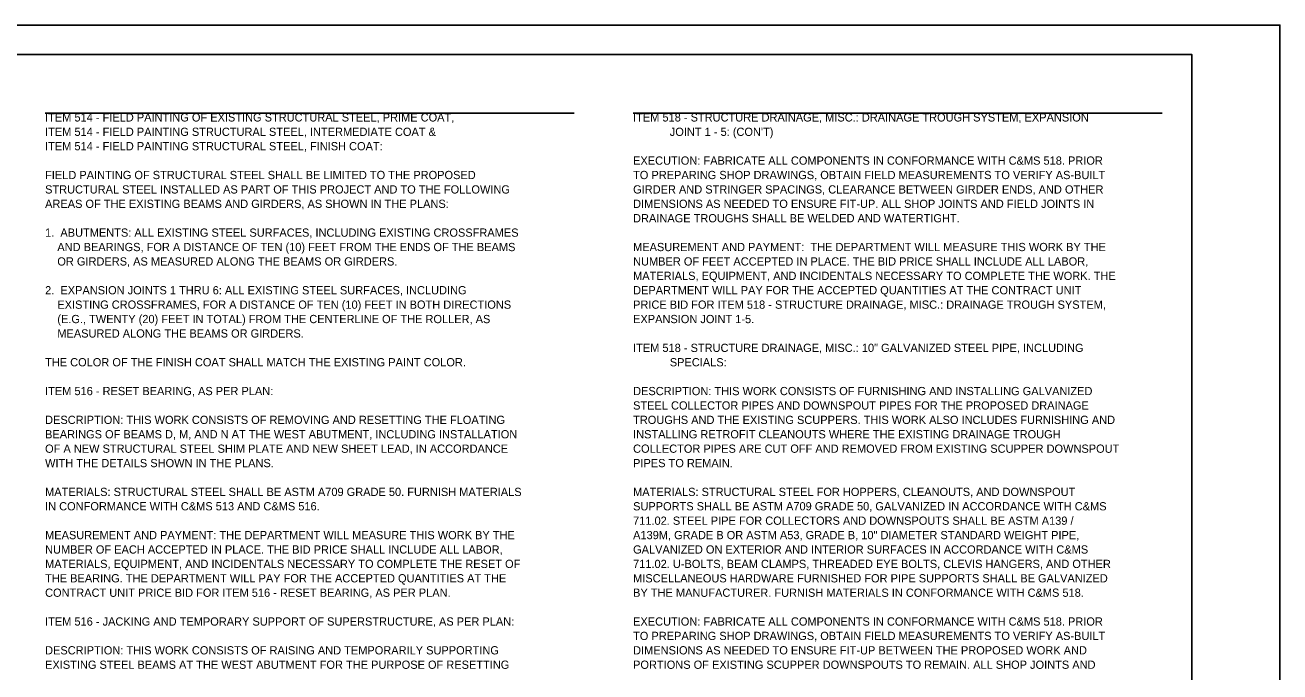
# Model space of a CAD drawing. Extents: x 0 to 72, y -26 to 50.
# Drawn here: x 50.66 to 72, y 37 to 48 of the extents above; entities that cross this region are included whole.
import ezdxf

# ---------------------------------------------------------------- set-up
doc = ezdxf.new("R2010")
doc.units = 0
doc.layers.add('SH_Cut_Line', color=7, linetype='Continuous')
doc.layers.add('SH_Data', color=7, linetype='Continuous')

msp = doc.modelspace()

# ---------------------------------------------------------------- linework, layer by layer
at = {"layer": 'SH_Cut_Line'}
for p, q in [((51, 46.5), (60, 46.5)), ((61, 46.5), (70, 46.5))]:
    msp.add_line(p, q, dxfattribs=at)
for points in [[(38, 48), (72, 48), (72, 26), (38, 26)], [(40, 47.5), (70.5, 47.5), (70.5, 26.5), (40, 26.5)]]:
    msp.add_lwpolyline(points, close=True, dxfattribs=at)

# ---------------------------------------------------------------- texts
at = {"layer": 'SH_Data'}
for s, p in [('ITEM 514 - FIELD PAINTING OF EXISTING STRUCTURAL STEEL, PRIME COAT,', (51, 46.36)), ('ITEM 514 - FIELD PAINTING OF EXISTING STRUCTURAL STEEL, PRIME COAT,', (51, 46.36)), ('ITEM 518 - STRUCTURE DRAINAGE, MISC.: DRAINAGE TROUGH SYSTEM, EXPANSION', (61, 46.36)), ('ITEM 518 - STRUCTURE DRAINAGE, MISC.: DRAINAGE TROUGH SYSTEM, EXPANSION', (61, 46.36)), ('ITEM 514 - FIELD PAINTING STRUCTURAL STEEL, INTERMEDIATE COAT &', (51, 46.115)), ('ITEM 514 - FIELD PAINTING STRUCTURAL STEEL, INTERMEDIATE COAT &', (51, 46.115)), ("            JOINT 1 - 5: (CON'T)", (61, 46.115)), ("            JOINT 1 - 5: (CON'T)", (61, 46.115)), ('ITEM 514 - FIELD PAINTING STRUCTURAL STEEL, FINISH COAT:', (51, 45.87)), ('ITEM 514 - FIELD PAINTING STRUCTURAL STEEL, FINISH COAT:', (51, 45.87)), ('EXECUTION: FABRICATE ALL COMPONENTS IN CONFORMANCE WITH C&MS 518. PRIOR ', (61, 45.625)), ('FIELD PAINTING OF STRUCTURAL STEEL SHALL BE LIMITED TO THE PROPOSED ', (51, 45.38)), ('TO PREPARING SHOP DRAWINGS, OBTAIN FIELD MEASUREMENTS TO VERIFY AS-BUILT ', (61, 45.38)), ('STRUCTURAL STEEL INSTALLED AS PART OF THIS PROJECT AND TO THE FOLLOWING ', (51, 45.135)), ('GIRDER AND STRINGER SPACINGS, CLEARANCE BETWEEN GIRDER ENDS, AND OTHER ', (61, 45.135)), ('AREAS OF THE EXISTING BEAMS AND GIRDERS, AS SHOWN IN THE PLANS:', (51, 44.89)), ('DIMENSIONS AS NEEDED TO ENSURE FIT-UP. ALL SHOP JOINTS AND FIELD JOINTS IN ', (61, 44.89)), ('DRAINAGE TROUGHS SHALL BE WELDED AND WATERTIGHT.', (61, 44.645)), ('1.  ABUTMENTS: ALL EXISTING STEEL SURFACES, INCLUDING EXISTING CROSSFRAMES ', (51, 44.4)), ('    AND BEARINGS, FOR A DISTANCE OF TEN (10) FEET FROM THE ENDS OF THE BEAMS ', (51, 44.155)), ('MEASUREMENT AND PAYMENT:  THE DEPARTMENT WILL MEASURE THIS WORK BY THE ', (61, 44.155)), ('    OR GIRDERS, AS MEASURED ALONG THE BEAMS OR GIRDERS.', (51, 43.91)), ('NUMBER OF FEET ACCEPTED IN PLACE. THE BID PRICE SHALL INCLUDE ALL LABOR, ', (61, 43.91)), ('MATERIALS, EQUIPMENT, AND INCIDENTALS NECESSARY TO COMPLETE THE WORK. THE ', (61, 43.665)), ('2.  EXPANSION JOINTS 1 THRU 6: ALL EXISTING STEEL SURFACES, INCLUDING', (51, 43.42)), ('DEPARTMENT WILL PAY FOR THE ACCEPTED QUANTITIES AT THE CONTRACT UNIT ', (61, 43.42)), ('    EXISTING CROSSFRAMES, FOR A DISTANCE OF TEN (10) FEET IN BOTH DIRECTIONS', (51, 43.175)), ('PRICE BID FOR ITEM 518 - STRUCTURE DRAINAGE, MISC.: DRAINAGE TROUGH SYSTEM, ', (61, 43.175)), ('    (E.G., TWENTY (20) FEET IN TOTAL) FROM THE CENTERLINE OF THE ROLLER, AS', (51, 42.93)), ('EXPANSION JOINT 1-5.', (61, 42.93)), ('    MEASURED ALONG THE BEAMS OR GIRDERS.', (51, 42.685)), ('ITEM 518 - STRUCTURE DRAINAGE, MISC.: 10" GALVANIZED STEEL PIPE, INCLUDING', (61, 42.44)), ('ITEM 518 - STRUCTURE DRAINAGE, MISC.: 10" GALVANIZED STEEL PIPE, INCLUDING', (61, 42.44)), ('THE COLOR OF THE FINISH COAT SHALL MATCH THE EXISTING PAINT COLOR.', (51, 42.195)), ('            SPECIALS:', (61, 42.195)), ('            SPECIALS:', (61, 42.195)), ('ITEM 516 - RESET BEARING, AS PER PLAN:', (51, 41.705)), ('ITEM 516 - RESET BEARING, AS PER PLAN:', (51, 41.705)), ('DESCRIPTION: THIS WORK CONSISTS OF FURNISHING AND INSTALLING GALVANIZED ', (61, 41.705)), ('STEEL COLLECTOR PIPES AND DOWNSPOUT PIPES FOR THE PROPOSED DRAINAGE ', (61, 41.46)), ('DESCRIPTION: THIS WORK CONSISTS OF REMOVING AND RESETTING THE FLOATING ', (51, 41.215)), ('TROUGHS AND THE EXISTING SCUPPERS. THIS WORK ALSO INCLUDES FURNISHING AND ', (61, 41.215)), ('BEARINGS OF BEAMS D, M, AND N AT THE WEST ABUTMENT, INCLUDING INSTALLATION ', (51, 40.97)), ('INSTALLING RETROFIT CLEANOUTS WHERE THE EXISTING DRAINAGE TROUGH ', (61, 40.97)), ('OF A NEW STRUCTURAL STEEL SHIM PLATE AND NEW SHEET LEAD, IN ACCORDANCE ', (51, 40.725)), ('COLLECTOR PIPES ARE CUT OFF AND REMOVED FROM EXISTING SCUPPER DOWNSPOUT ', (61, 40.725)), ('WITH THE DETAILS SHOWN IN THE PLANS.', (51, 40.48)), ('PIPES TO REMAIN.', (61, 40.48)), ('MATERIALS: STRUCTURAL STEEL SHALL BE ASTM A709 GRADE 50. FURNISH MATERIALS ', (51, 39.99)), ('MATERIALS: STRUCTURAL STEEL FOR HOPPERS, CLEANOUTS, AND DOWNSPOUT ', (61, 39.99)), ('IN CONFORMANCE WITH C&MS 513 AND C&MS 516.', (51, 39.745)), ('SUPPORTS SHALL BE ASTM A709 GRADE 50, GALVANIZED IN ACCORDANCE WITH C&MS ', (61, 39.745)), ('711.02. STEEL PIPE FOR COLLECTORS AND DOWNSPOUTS SHALL BE ASTM A139 / ', (61, 39.5)), ('MEASUREMENT AND PAYMENT: THE DEPARTMENT WILL MEASURE THIS WORK BY THE ', (51, 39.255)), ('A139M, GRADE B OR ASTM A53, GRADE B, 10" DIAMETER STANDARD WEIGHT PIPE, ', (61, 39.255)), ('NUMBER OF EACH ACCEPTED IN PLACE. THE BID PRICE SHALL INCLUDE ALL LABOR, ', (51, 39.01)), ('GALVANIZED ON EXTERIOR AND INTERIOR SURFACES IN ACCORDANCE WITH C&MS ', (61, 39.01)), ('MATERIALS, EQUIPMENT, AND INCIDENTALS NECESSARY TO COMPLETE THE RESET OF ', (51, 38.765)), ('711.02. U-BOLTS, BEAM CLAMPS, THREADED EYE BOLTS, CLEVIS HANGERS, AND OTHER ', (61, 38.765)), ('THE BEARING. THE DEPARTMENT WILL PAY FOR THE ACCEPTED QUANTITIES AT THE ', (51, 38.52)), ('MISCELLANEOUS HARDWARE FURNISHED FOR PIPE SUPPORTS SHALL BE GALVANIZED ', (61, 38.52)), ('CONTRACT UNIT PRICE BID FOR ITEM 516 - RESET BEARING, AS PER PLAN.', (51, 38.275)), ('BY THE MANUFACTURER. FURNISH MATERIALS IN CONFORMANCE WITH C&MS 518.', (61, 38.275)), ('ITEM 516 - JACKING AND TEMPORARY SUPPORT OF SUPERSTRUCTURE, AS PER PLAN:', (51, 37.785)), ('ITEM 516 - JACKING AND TEMPORARY SUPPORT OF SUPERSTRUCTURE, AS PER PLAN:', (51, 37.785)), ('EXECUTION: FABRICATE ALL COMPONENTS IN CONFORMANCE WITH C&MS 518. PRIOR ', (61, 37.785)), ('TO PREPARING SHOP DRAWINGS, OBTAIN FIELD MEASUREMENTS TO VERIFY AS-BUILT ', (61, 37.54)), ('DESCRIPTION: THIS WORK CONSISTS OF RAISING AND TEMPORARILY SUPPORTING ', (51, 37.295)), ('DIMENSIONS AS NEEDED TO ENSURE FIT-UP BETWEEN THE PROPOSED WORK AND', (61, 37.295)), ('EXISTING STEEL BEAMS AT THE WEST ABUTMENT FOR THE PURPOSE OF RESETTING ', (51, 37.05)), ('PORTIONS OF EXISTING SCUPPER DOWNSPOUTS TO REMAIN. ALL SHOP JOINTS AND', (61, 37.05))]:
    msp.add_text(s, height=0.14, dxfattribs=at).set_placement(p)

doc.saveas('drawing.dxf')
